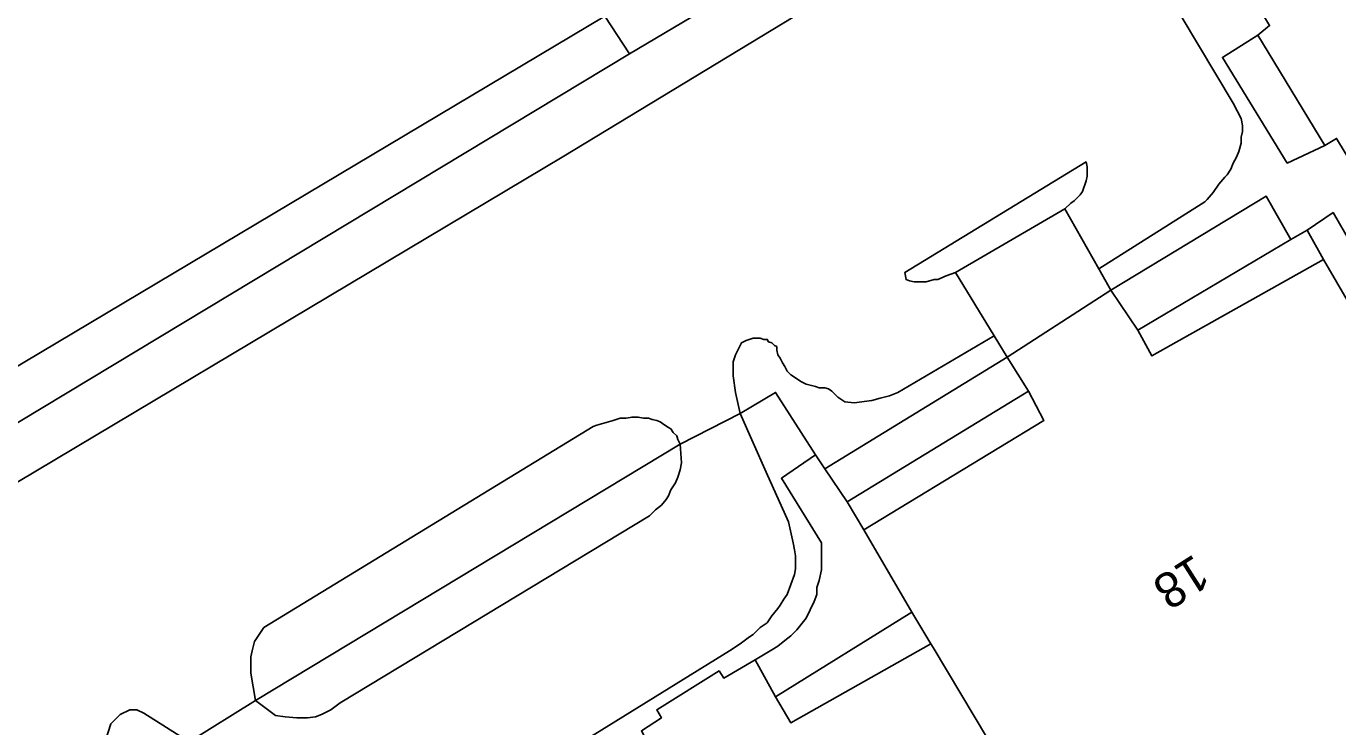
# Model space of a CAD drawing. Extents: x 529240 to 530363, y 179600 to 180767.
# Drawn here: x 529829.9 to 529885.7, y 180307.1 to 180336.9 of the extents above; entities that cross this region are included whole.
import ezdxf

# ---------------------------------------------------------------- set-up
doc = ezdxf.new("R2010")
doc.units = 0
for name, color, linetype in [('Building', 7, 'Continuous'), ('General surface', 7, 'Continuous'), ('Road Or Track', 7, 'Continuous'), ('Roadside', 7, 'Continuous'), ('Unclassified', 7, 'Continuous')]:
    doc.layers.add(name, color=color, linetype=linetype)

msp = doc.modelspace()

# ---------------------------------------------------------------- linework, layer by layer
at = {"layer": 'Building'}
for points in [[(529825.6, 180320.1), (529854.55, 180337.35), (529857.25, 180338.95), (529866.86, 180344.8), (529865.7, 180346.7), (529864.65, 180348.35), (529862.1, 180352.4), (529858.75, 180357.8), (529856.65, 180356.6), (529853.3, 180361.85), (529852.65, 180362.95), (529851.2, 180365.2), (529854.95, 180367.7), (529854.5, 180368.4), (529850.75, 180374.4), (529842.65, 180369.35), (529827.25, 180359.8)], [(529874.55, 180349.45), (529875.5, 180347.85), (529876.05, 180348.15), (529882.8, 180336.95), (529882.3, 180336.55)], [(529825.6, 180320.1), (529854.55, 180337.35)], [(529854.55, 180337.35), (529855.6, 180335.75)], [(529882.3, 180336.55), (529885.15, 180331.85)], [(529825.85, 180319.7), (529826.65, 180318.3), (529855.6, 180335.75)], [(529885.15, 180331.85), (529885.65, 180332.15), (529887.25, 180329.5), (529886.75, 180329.2), (529887.3, 180328.3)], [(529874.1, 180329.15), (529869.45, 180326.45)], [(529875.55, 180326.6), (529874.1, 180329.15)], [(529883.7, 180327.85), (529877.2, 180324)], [(529884.4, 180328.25), (529883.7, 180327.85)], [(529884.4, 180328.25), (529885.1, 180327)], [(529877.2, 180324), (529877.8, 180322.9), (529885.1, 180327)], [(529885.1, 180327), (529898.35, 180304.2)], [(529869.45, 180326.45), (529871.1, 180323.75)], [(529876.05, 180325.7), (529875.55, 180326.6)], [(529871.65, 180322.85), (529876.05, 180325.7)], [(529877.2, 180324), (529876.05, 180325.7)], [(529871.1, 180323.75), (529871.65, 180322.85)], [(529871.65, 180322.85), (529872.55, 180321.4)], [(529872.55, 180321.4), (529864.85, 180316.7)], [(529865.55, 180315.5), (529873.2, 180320.15), (529872.55, 180321.4)], [(529865.55, 180315.5), (529864.85, 180316.7)], [(529867.6, 180312), (529865.55, 180315.5)], [(529861.8, 180308.4), (529867.6, 180312)], [(529868.4, 180310.65), (529867.6, 180312)], [(529861.8, 180308.4), (529862.45, 180307.3), (529868.4, 180310.65)], [(529879, 180292.9), (529868.5, 180310.5), (529868.4, 180310.65)], [(529856.1, 180306.95), (529856.95, 180307.5), (529856.75, 180307.85), (529859.4, 180309.5), (529859.6, 180309.2), (529860.94, 180309.98)], [(529860.94, 180309.98), (529861.8, 180308.4)]]:
    msp.add_lwpolyline(points, dxfattribs=at)
for points in [[(529873.5, 180351.3), (529874.55, 180349.45), (529875.5, 180347.85), (529876.05, 180348.15), (529882.8, 180336.95), (529882.3, 180336.55), (529885.15, 180331.85), (529885.65, 180332.15), (529887.25, 180329.5), (529886.75, 180329.2), (529887.3, 180328.3), (529895.4, 180315.2), (529914.15, 180326.65), (529904.15, 180343.05), (529897.9, 180339.5), (529896.15, 180338.5), (529888.3, 180351.5), (529886.1, 180355.05), (529881.5, 180352.25), (529879.85, 180355.05)], [(529855.6, 180335.75), (529858.2, 180337.3), (529857.25, 180338.95), (529854.55, 180337.35)], [(529825.85, 180319.7), (529826.65, 180318.3), (529855.6, 180335.75), (529854.55, 180337.35), (529825.6, 180320.1)], [(529885.15, 180331.85), (529882.3, 180336.55), (529880.8, 180335.6), (529883.55, 180331.1)], [(529871.65, 180322.85), (529876.05, 180325.7), (529875.55, 180326.6), (529874.1, 180329.15), (529869.45, 180326.45), (529871.1, 180323.75)], [(529877.2, 180324), (529877.8, 180322.9), (529885.1, 180327), (529884.4, 180328.25), (529883.7, 180327.85)], [(529872.55, 180321.4), (529873.2, 180320.15), (529865.55, 180315.5), (529867.6, 180312), (529868.4, 180310.65), (529868.5, 180310.5), (529879, 180292.9), (529880.5, 180290.4), (529897.8, 180300.85), (529896.7, 180302.7), (529898.5, 180303.95), (529898.35, 180304.2), (529885.1, 180327), (529877.8, 180322.9), (529877.2, 180324), (529876.05, 180325.7), (529871.65, 180322.85)], [(529872.55, 180321.4), (529864.85, 180316.7), (529865.55, 180315.5), (529873.2, 180320.15)], [(529867.6, 180312), (529861.8, 180308.4), (529862.45, 180307.3), (529868.4, 180310.65)], [(529856.9, 180305.45), (529857.6, 180304.25), (529855.1, 180302.8), (529865.9, 180285.15), (529879, 180292.9), (529868.5, 180310.5), (529868.4, 180310.65), (529862.45, 180307.3), (529861.8, 180308.4), (529860.94, 180309.98), (529859.6, 180309.2), (529859.4, 180309.5), (529856.75, 180307.85), (529856.95, 180307.5), (529856.1, 180306.95)]]:
    msp.add_lwpolyline(points, close=True, dxfattribs=at)
at = {"layer": 'General surface'}
for points in [[(529876.05, 180325.7), (529877.2, 180324), (529883.7, 180327.85), (529882.65, 180329.7)], [(529884.4, 180328.25), (529885.1, 180327), (529898.35, 180304.2), (529899.4, 180304.85), (529898.05, 180307.2), (529886.25, 180327.7), (529885.5, 180329)], [(529871.65, 180322.85), (529863.9, 180318.1), (529864.85, 180316.7), (529872.55, 180321.4)], [(529864.85, 180316.7), (529863.9, 180318.1), (529863.5, 180318.7), (529862.05, 180317.7), (529863.75, 180314.95), (529863.75, 180313.8), (529863.65, 180313.35), (529863.55, 180313.05), (529863.55, 180312.75), (529863.45, 180312.45), (529863.1, 180311.75), (529862.7, 180311.25), (529862.45, 180311), (529862.2, 180310.8), (529861.9, 180310.55), (529861.65, 180310.4), (529860.94, 180309.98), (529861.8, 180308.4), (529867.6, 180312), (529865.55, 180315.5)]]:
    msp.add_lwpolyline(points, close=True, dxfattribs=at)
msp.add_lwpolyline([(529853.05, 180306.15), (529859.85, 180310.35), (529860.3, 180310.65), (529860.7, 180310.95), (529860.85, 180311.05), (529861.15, 180311.35), (529861.45, 180311.55), (529861.65, 180311.85), (529861.9, 180312.15), (529862, 180312.3), (529862.15, 180312.55), (529862.3, 180312.75), (529862.6, 180313.6), (529862.65, 180313.85), (529862.65, 180314.4), (529862.6, 180314.65), (529862.55, 180314.95), (529862.5, 180315.2), (529862.35, 180315.85), (529861.4, 180317.95), (529860.3, 180320.45), (529857.75, 180319.15), (529857.8, 180318.35), (529857.75, 180318.05), (529857.65, 180317.75), (529857.55, 180317.5), (529857.35, 180317.2), (529857.25, 180316.95), (529857.15, 180316.8), (529856.95, 180316.55), (529856.7, 180316.35), (529856.45, 180316.1), (529843.3, 180308.15), (529842.9, 180307.85), (529842.5, 180307.65), (529842.25, 180307.55), (529841.9, 180307.5), (529841.45, 180307.5), (529840.95, 180307.55), (529840.55, 180307.6), (529839.7, 180308.25), (529836.87, 180306.48)], dxfattribs=at)
at = {"layer": 'Road Or Track'}
for points in [[(529870.5, 180342.15), (529852.8, 180331.4), (529822.05, 180313.05)], [(529822.05, 180313.05), (529852.8, 180331.4), (529870.5, 180342.15)], [(529833.3, 180306.5), (529833.55, 180307.25), (529833.95, 180307.65), (529834.35, 180307.85), (529834.65, 180307.85), (529834.95, 180307.7), (529836.87, 180306.48), (529839.7, 180308.25), (529839.5, 180309.4), (529839.5, 180310.1), (529839.55, 180310.35), (529839.65, 180310.75), (529840.05, 180311.35), (529854.05, 180319.9), (529854.2, 180319.95), (529854.9, 180320.15), (529855.2, 180320.25), (529855.45, 180320.25), (529855.7, 180320.3), (529855.95, 180320.3), (529856.2, 180320.25), (529856.4, 180320.25), (529856.55, 180320.2), (529856.75, 180320.15), (529856.9, 180320.1), (529857.1, 180319.95), (529857.25, 180319.85), (529857.35, 180319.8), (529857.45, 180319.65), (529857.6, 180319.5), (529857.65, 180319.35), (529857.75, 180319.15), (529860.3, 180320.45), (529860.1, 180321.35), (529860, 180322.05), (529860, 180322.65), (529860.1, 180322.95), (529860.35, 180323.45), (529860.55, 180323.55), (529860.85, 180323.65), (529861.15, 180323.65), (529861.3, 180323.6), (529861.45, 180323.6), (529861.5, 180323.5), (529861.65, 180323.45), (529861.75, 180323.35), (529861.85, 180323.3), (529861.85, 180323.15), (529861.9, 180322.95), (529862, 180322.8), (529862.1, 180322.6), (529862.2, 180322.45), (529862.3, 180322.25), (529862.45, 180322.1), (529862.9, 180321.8), (529863.1, 180321.7), (529863.5, 180321.6), (529863.65, 180321.55), (529863.9, 180321.55), (529864.05, 180321.5), (529864.2, 180321.4), (529864.45, 180321.15), (529864.75, 180320.95), (529865.15, 180320.9), (529865.9, 180321), (529866.25, 180321.1), (529866.65, 180321.2), (529867, 180321.35), (529871.1, 180323.75), (529869.45, 180326.45), (529869.05, 180326.3), (529868.7, 180326.15), (529868.55, 180326.15), (529868.2, 180326.05), (529867.7, 180326.05), (529867.5, 180326.1), (529867.35, 180326.15), (529867.3, 180326.45), (529875, 180331.15), (529875.05, 180330.95), (529875.05, 180330.55), (529875, 180330.35), (529874.85, 180329.9), (529874.75, 180329.75), (529874.5, 180329.5), (529874.35, 180329.4), (529874.1, 180329.15), (529875.55, 180326.6), (529880.05, 180329.45), (529880.15, 180329.55), (529880.4, 180329.85), (529880.65, 180330.2), (529880.9, 180330.5), (529881, 180330.6), (529881.15, 180330.85), (529881.25, 180331.1), (529881.4, 180331.35), (529881.5, 180331.6), (529881.6, 180331.95), (529881.6, 180332.2), (529881.65, 180332.45), (529881.65, 180332.7), (529881.6, 180333), (529881.25, 180333.65), (529876.1, 180342.3)], [(529876.1, 180342.3), (529881.25, 180333.65), (529881.6, 180333), (529881.65, 180332.7), (529881.65, 180332.45), (529881.6, 180332.2), (529881.6, 180331.95), (529881.5, 180331.6), (529881.4, 180331.35), (529881.25, 180331.1), (529881.15, 180330.85), (529881, 180330.6), (529880.9, 180330.5), (529880.65, 180330.2), (529880.4, 180329.85), (529880.15, 180329.55), (529880.05, 180329.45), (529875.55, 180326.6)], [(529875, 180331.15), (529867.3, 180326.45)], [(529871.1, 180323.75), (529867, 180321.35), (529866.65, 180321.2), (529866.25, 180321.1), (529865.9, 180321), (529865.15, 180320.9), (529864.75, 180320.95), (529864.45, 180321.15), (529864.2, 180321.4), (529864.05, 180321.5), (529863.9, 180321.55), (529863.65, 180321.55), (529863.5, 180321.6), (529863.1, 180321.7), (529862.9, 180321.8), (529862.45, 180322.1), (529862.3, 180322.25), (529862.2, 180322.45), (529862.1, 180322.6), (529862, 180322.8), (529861.9, 180322.95), (529861.85, 180323.15), (529861.85, 180323.3), (529861.75, 180323.35), (529861.65, 180323.45), (529861.5, 180323.5), (529861.45, 180323.6), (529861.3, 180323.6), (529861.15, 180323.65), (529860.85, 180323.65), (529860.55, 180323.55), (529860.35, 180323.45), (529860.1, 180322.95), (529860, 180322.65), (529860, 180322.05), (529860.1, 180321.35), (529860.3, 180320.45)], [(529857.75, 180319.15), (529857.65, 180319.35), (529857.6, 180319.5), (529857.45, 180319.65), (529857.35, 180319.8), (529857.25, 180319.85), (529857.1, 180319.95), (529856.9, 180320.1), (529856.75, 180320.15), (529856.55, 180320.2), (529856.4, 180320.25), (529856.2, 180320.25), (529855.95, 180320.3), (529855.7, 180320.3), (529855.45, 180320.25), (529855.2, 180320.25), (529854.9, 180320.15), (529854.2, 180319.95), (529854.05, 180319.9), (529840.05, 180311.35), (529839.65, 180310.75)], [(529839.65, 180310.75), (529839.55, 180310.35), (529839.5, 180310.1), (529839.5, 180309.4), (529839.7, 180308.25)], [(529836.87, 180306.48), (529834.95, 180307.7), (529834.65, 180307.85), (529834.35, 180307.85), (529833.95, 180307.65), (529833.55, 180307.25), (529833.3, 180306.5), (529833.25, 180306.3), (529833.25, 180305.55), (529833.35, 180305.05), (529833.55, 180304.55), (529833.6, 180304.4)]]:
    msp.add_lwpolyline(points, dxfattribs=at)
at = {"layer": 'Roadside'}
for points in [[(529822.05, 180313.05), (529852.8, 180331.4), (529870.5, 180342.15)], [(529876.1, 180342.3), (529881.25, 180333.65), (529881.6, 180333), (529881.65, 180332.7), (529881.65, 180332.45), (529881.6, 180332.2), (529881.6, 180331.95), (529881.5, 180331.6), (529881.4, 180331.35), (529881.25, 180331.1), (529881.15, 180330.85), (529881, 180330.6), (529880.9, 180330.5), (529880.65, 180330.2), (529880.4, 180329.85), (529880.15, 180329.55), (529880.05, 180329.45), (529875.55, 180326.6), (529876.05, 180325.7), (529882.65, 180329.7), (529883.7, 180327.85), (529884.4, 180328.25), (529885.5, 180329), (529886.25, 180327.7)], [(529858.2, 180337.3), (529855.6, 180335.75), (529826.65, 180318.3)], [(529887.25, 180329.5), (529885.65, 180332.15), (529885.15, 180331.85), (529883.55, 180331.1), (529880.8, 180335.6), (529882.3, 180336.55), (529882.8, 180336.95)], [(529856.1, 180306.95), (529856.95, 180307.5), (529856.75, 180307.85), (529859.4, 180309.5), (529859.6, 180309.2), (529860.94, 180309.98), (529861.65, 180310.4), (529861.9, 180310.55), (529862.2, 180310.8), (529862.45, 180311), (529862.7, 180311.25), (529863.1, 180311.75), (529863.45, 180312.45), (529863.55, 180312.75), (529863.55, 180313.05), (529863.65, 180313.35), (529863.75, 180313.8), (529863.75, 180314.95), (529862.05, 180317.7), (529863.5, 180318.7), (529861.8, 180321.35), (529860.3, 180320.45), (529861.4, 180317.95), (529862.35, 180315.85), (529862.5, 180315.2), (529862.55, 180314.95), (529862.6, 180314.65), (529862.65, 180314.4), (529862.65, 180313.85), (529862.6, 180313.6), (529862.3, 180312.75), (529862.15, 180312.55), (529862, 180312.3), (529861.9, 180312.15), (529861.65, 180311.85), (529861.45, 180311.55), (529861.15, 180311.35), (529860.85, 180311.05), (529860.7, 180310.95), (529860.3, 180310.65), (529859.85, 180310.35), (529853.05, 180306.15)], [(529836.87, 180306.48), (529834.95, 180307.7), (529834.65, 180307.85), (529834.35, 180307.85), (529833.95, 180307.65), (529833.55, 180307.25), (529833.3, 180306.5)]]:
    msp.add_lwpolyline(points, dxfattribs=at)
for points in [[(529874.1, 180329.15), (529874.35, 180329.4), (529874.5, 180329.5), (529874.75, 180329.75), (529874.85, 180329.9), (529875, 180330.35), (529875.05, 180330.55), (529875.05, 180330.95), (529875, 180331.15), (529867.3, 180326.45), (529867.35, 180326.15), (529867.5, 180326.1), (529867.7, 180326.05), (529868.2, 180326.05), (529868.55, 180326.15), (529868.7, 180326.15), (529869.05, 180326.3), (529869.45, 180326.45)], [(529871.1, 180323.75), (529867, 180321.35), (529866.65, 180321.2), (529866.25, 180321.1), (529865.9, 180321), (529865.15, 180320.9), (529864.75, 180320.95), (529864.45, 180321.15), (529864.2, 180321.4), (529864.05, 180321.5), (529863.9, 180321.55), (529863.65, 180321.55), (529863.5, 180321.6), (529863.1, 180321.7), (529862.9, 180321.8), (529862.45, 180322.1), (529862.3, 180322.25), (529862.2, 180322.45), (529862.1, 180322.6), (529862, 180322.8), (529861.9, 180322.95), (529861.85, 180323.15), (529861.85, 180323.3), (529861.75, 180323.35), (529861.65, 180323.45), (529861.5, 180323.5), (529861.45, 180323.6), (529861.3, 180323.6), (529861.15, 180323.65), (529860.85, 180323.65), (529860.55, 180323.55), (529860.35, 180323.45), (529860.1, 180322.95), (529860, 180322.65), (529860, 180322.05), (529860.1, 180321.35), (529860.3, 180320.45), (529861.8, 180321.35), (529863.5, 180318.7), (529863.9, 180318.1), (529871.65, 180322.85)], [(529839.65, 180310.75), (529839.55, 180310.35), (529839.5, 180310.1), (529839.5, 180309.4), (529839.7, 180308.25), (529857.75, 180319.15), (529857.65, 180319.35), (529857.6, 180319.5), (529857.45, 180319.65), (529857.35, 180319.8), (529857.25, 180319.85), (529857.1, 180319.95), (529856.9, 180320.1), (529856.75, 180320.15), (529856.55, 180320.2), (529856.4, 180320.25), (529856.2, 180320.25), (529855.95, 180320.3), (529855.7, 180320.3), (529855.45, 180320.25), (529855.2, 180320.25), (529854.9, 180320.15), (529854.2, 180319.95), (529854.05, 180319.9), (529840.05, 180311.35)], [(529857.75, 180319.15), (529839.7, 180308.25), (529840.55, 180307.6), (529840.95, 180307.55), (529841.45, 180307.5), (529841.9, 180307.5), (529842.25, 180307.55), (529842.5, 180307.65), (529842.9, 180307.85), (529843.3, 180308.15), (529856.45, 180316.1), (529856.7, 180316.35), (529856.95, 180316.55), (529857.15, 180316.8), (529857.25, 180316.95), (529857.35, 180317.2), (529857.55, 180317.5), (529857.65, 180317.75), (529857.75, 180318.05), (529857.8, 180318.35)]]:
    msp.add_lwpolyline(points, close=True, dxfattribs=at)
at = {"layer": 'Unclassified'}
for points in [[(529855.6, 180335.75), (529858.2, 180337.3)], [(529882.3, 180336.55), (529880.8, 180335.6), (529883.55, 180331.1), (529885.15, 180331.85)], [(529874.1, 180329.15), (529874.35, 180329.4), (529874.5, 180329.5), (529874.75, 180329.75), (529874.85, 180329.9), (529875, 180330.35), (529875.05, 180330.55), (529875.05, 180330.95), (529875, 180331.15)], [(529876.05, 180325.7), (529882.65, 180329.7), (529883.7, 180327.85)], [(529886.25, 180327.7), (529885.5, 180329), (529884.4, 180328.25)], [(529869.45, 180326.45), (529869.05, 180326.3), (529868.7, 180326.15), (529868.55, 180326.15), (529868.2, 180326.05), (529867.7, 180326.05), (529867.5, 180326.1), (529867.35, 180326.15), (529867.3, 180326.45)], [(529871.65, 180322.85), (529863.9, 180318.1)], [(529861.8, 180321.35), (529860.3, 180320.45)], [(529863.5, 180318.7), (529861.8, 180321.35)], [(529860.3, 180320.45), (529861.4, 180317.95), (529862.35, 180315.85), (529862.5, 180315.2), (529862.55, 180314.95), (529862.6, 180314.65), (529862.65, 180314.4), (529862.65, 180313.85), (529862.6, 180313.6), (529862.3, 180312.75), (529862.15, 180312.55), (529862, 180312.3), (529861.9, 180312.15), (529861.65, 180311.85), (529861.45, 180311.55), (529861.15, 180311.35), (529860.85, 180311.05), (529860.7, 180310.95), (529860.3, 180310.65), (529859.85, 180310.35), (529853.05, 180306.15)], [(529857.75, 180319.15), (529860.3, 180320.45)], [(529839.7, 180308.25), (529840.55, 180307.6), (529840.95, 180307.55), (529841.45, 180307.5), (529841.9, 180307.5), (529842.25, 180307.55), (529842.5, 180307.65), (529842.9, 180307.85), (529843.3, 180308.15), (529856.45, 180316.1), (529856.7, 180316.35), (529856.95, 180316.55), (529857.15, 180316.8), (529857.25, 180316.95), (529857.35, 180317.2), (529857.55, 180317.5), (529857.65, 180317.75), (529857.75, 180318.05), (529857.8, 180318.35), (529857.75, 180319.15)], [(529857.75, 180319.15), (529839.7, 180308.25)], [(529860.94, 180309.98), (529861.65, 180310.4), (529861.9, 180310.55), (529862.2, 180310.8), (529862.45, 180311), (529862.7, 180311.25), (529863.1, 180311.75), (529863.45, 180312.45), (529863.55, 180312.75), (529863.55, 180313.05), (529863.65, 180313.35), (529863.75, 180313.8), (529863.75, 180314.95), (529862.05, 180317.7), (529863.5, 180318.7)], [(529863.9, 180318.1), (529863.5, 180318.7)], [(529864.85, 180316.7), (529863.9, 180318.1)], [(529836.87, 180306.48), (529839.7, 180308.25)]]:
    msp.add_lwpolyline(points, dxfattribs=at)

# ---------------------------------------------------------------- texts
msp.add_text('18', height=1.5, rotation=212.5, dxfattribs=at).set_placement((529879.6, 180314.5))

doc.saveas('drawing.dxf')
